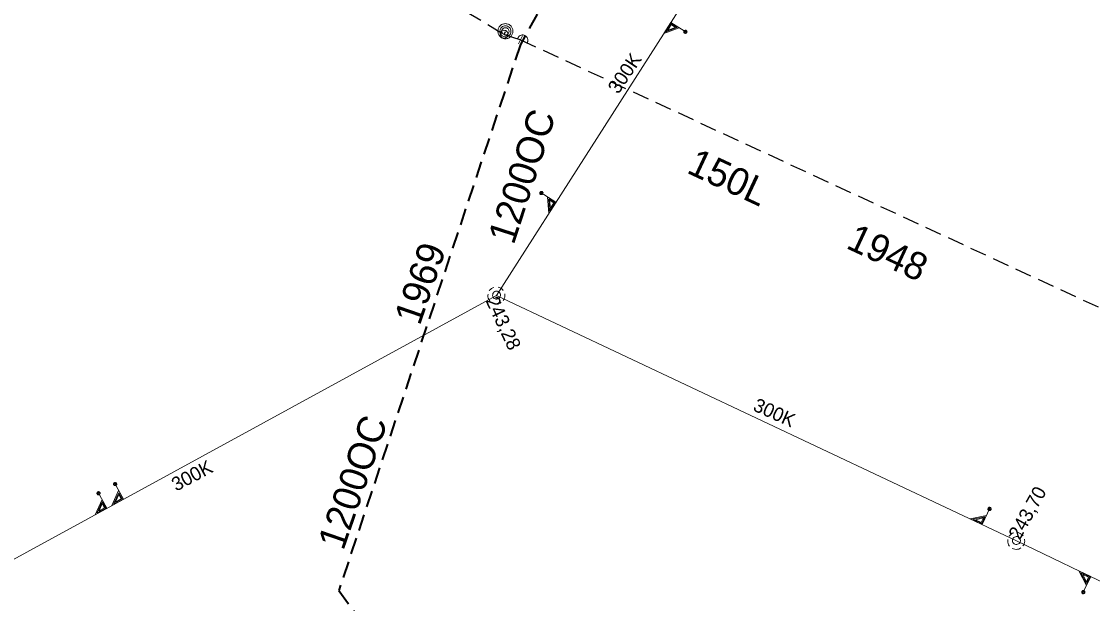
# Model space of a CAD drawing. Extents: x -735085 to -733500, y -1044153 to -1043402.
# Drawn here: x -734712.5 to -734650.3, y -1043643.2 to -1043609.3 of the extents above; entities that cross this region are included whole.
import ezdxf

# ---------------------------------------------------------------- set-up
doc = ezdxf.new("R2010")
doc.units = 0
doc.header["$LTSCALE"] = 0.32
doc.linetypes.add('MEDIUM_DASHED', pattern=[4.5, 3, -1.5])
doc.layers.add('15', color=7, linetype='Continuous')
doc.layers.add('16', color=7, linetype='Continuous')
for name, color, linetype, lineweight in [('18', 7, 'Continuous', 13), ('20', 7, 'Continuous', 13), ('8', 7, 'Continuous', 13)]:
    doc.layers.add(name, color=color, linetype=linetype, lineweight=lineweight)

msp = doc.modelspace()

# ---------------------------------------------------------------- linework, layer by layer
at = {"layer": '18'}
for points in [[(-734673.843, -1043609.992), (-734674.766, -1043609.403), (-734675.181, -1043610.053), (-734674.279, -1043609.714)], [(-734674.406, -1043609.693), (-734674.757, -1043609.469), (-734675.062, -1043609.946), (-734674.405, -1043609.694)], [(-734674.502, -1043609.688), (-734674.748, -1043609.531), (-734674.947, -1043609.844), (-734674.501, -1043609.687)], [(-734682.366, -1043619.262), (-734681.443, -1043619.851), (-734681.857, -1043620.5), (-734681.93, -1043619.54)], [(-734681.857, -1043619.646), (-734681.507, -1043619.87), (-734681.811, -1043620.347), (-734681.858, -1043619.645)], [(-734681.812, -1043619.731), (-734681.566, -1043619.888), (-734681.766, -1043620.201), (-734681.811, -1043619.73)], [(-734685.043, -1043624.797), (-734685.114, -1043624.825), (-734685.181, -1043624.864), (-734685.241, -1043624.912), (-734685.292, -1043624.969), (-734685.316, -1043625.003)], [(-734684.502, -1043624.98), (-734684.552, -1043624.922), (-734684.61, -1043624.872), (-734684.675, -1043624.831), (-734684.746, -1043624.802), (-734684.795, -1043624.788)], [(-734685.388, -1043625.189), (-734685.394, -1043625.266), (-734685.389, -1043625.343), (-734685.372, -1043625.418), (-734685.343, -1043625.489), (-734685.303, -1043625.555), (-734685.287, -1043625.577)], [(-734684.507, -1043625.566), (-734684.466, -1043625.501), (-734684.435, -1043625.431), (-734684.416, -1043625.356), (-734684.408, -1043625.28), (-734684.413, -1043625.203), (-734684.419, -1043625.168)], [(-734685.13, -1043625.706), (-734685.06, -1043625.737), (-734684.985, -1043625.756), (-734684.909, -1043625.763), (-734684.832, -1043625.758), (-734684.757, -1043625.741), (-734684.685, -1043625.713), (-734684.625, -1043625.678)], [(-734708.053, -1043636.676), (-734707.528, -1043637.637), (-734708.203, -1043638.007), (-734707.805, -1043637.13)], [(-734707.088, -1043636.148), (-734706.563, -1043637.109), (-734707.238, -1043637.479), (-734706.84, -1043636.602)], [(-734706.827, -1043636.729), (-734706.628, -1043637.094), (-734707.124, -1043637.366), (-734706.828, -1043636.729)], [(-734707.792, -1043637.257), (-734707.593, -1043637.622), (-734708.089, -1043637.894), (-734707.793, -1043637.257)], [(-734707.793, -1043637.354), (-734707.653, -1043637.61), (-734707.98, -1043637.788), (-734707.792, -1043637.353)], [(-734706.828, -1043636.826), (-734706.688, -1043637.082), (-734707.015, -1043637.26), (-734706.827, -1043636.825)], [(-734656.218, -1043637.586), (-734656.686, -1043638.576), (-734657.382, -1043638.247), (-734656.439, -1043638.053)], [(-734656.534, -1043638.139), (-734656.712, -1043638.515), (-734657.224, -1043638.273), (-734656.534, -1043638.138)], [(-734656.613, -1043638.194), (-734656.738, -1043638.458), (-734657.074, -1043638.3), (-734656.612, -1043638.195)], [(-734654.852, -1043639.057), (-734654.923, -1043639.085), (-734654.99, -1043639.124), (-734655.05, -1043639.172), (-734655.101, -1043639.229), (-734655.125, -1043639.263)], [(-734654.311, -1043639.24), (-734654.361, -1043639.182), (-734654.419, -1043639.132), (-734654.484, -1043639.091), (-734654.555, -1043639.062), (-734654.604, -1043639.048)], [(-734655.197, -1043639.449), (-734655.203, -1043639.526), (-734655.198, -1043639.603), (-734655.181, -1043639.678), (-734655.152, -1043639.749), (-734655.112, -1043639.815), (-734655.096, -1043639.837)], [(-734654.316, -1043639.826), (-734654.275, -1043639.761), (-734654.244, -1043639.691), (-734654.225, -1043639.616), (-734654.217, -1043639.54), (-734654.222, -1043639.463), (-734654.228, -1043639.428)], [(-734654.939, -1043639.966), (-734654.869, -1043639.997), (-734654.794, -1043640.016), (-734654.718, -1043640.023), (-734654.641, -1043640.018), (-734654.566, -1043640.001), (-734654.494, -1043639.973), (-734654.434, -1043639.938)], [(-734650.854, -1043642.594), (-734650.378, -1043641.608), (-734651.072, -1043641.273), (-734650.63, -1043642.129)], [(-734650.624, -1043642), (-734650.443, -1043641.625), (-734650.952, -1043641.379), (-734650.625, -1043642.001)], [(-734650.63, -1043641.904), (-734650.503, -1043641.641), (-734650.837, -1043641.48), (-734650.629, -1043641.905)]]:
    msp.add_lwpolyline(points, dxfattribs=at)
for points in [[(-734673.973, -1043610.022), (-734673.942, -1043610.035), (-734673.909, -1043610.036), (-734673.877, -1043610.025), (-734673.851, -1043610.004), (-734673.834, -1043609.975), (-734673.829, -1043609.942), (-734673.834, -1043609.909), (-734673.852, -1043609.88), (-734673.877, -1043609.859), (-734673.91, -1043609.849), (-734673.943, -1043609.85), (-734673.974, -1043609.863), (-734673.998, -1043609.886), (-734674.013, -1043609.916), (-734674.017, -1043609.949), (-734674.008, -1043609.982), (-734673.989, -1043610.009)], [(-734673.96, -1043609.998), (-734673.933, -1043610.008), (-734673.905, -1043610.006), (-734673.88, -1043609.993), (-734673.863, -1043609.97), (-734673.857, -1043609.943), (-734673.861, -1043609.915), (-734673.877, -1043609.892), (-734673.902, -1043609.877), (-734673.93, -1043609.875), (-734673.957, -1043609.883), (-734673.979, -1043609.902), (-734673.99, -1043609.927), (-734673.989, -1043609.956), (-734673.978, -1043609.982)], [(-734682.337, -1043619.392), (-734682.306, -1043619.405), (-734682.272, -1043619.406), (-734682.241, -1043619.395), (-734682.215, -1043619.374), (-734682.198, -1043619.345), (-734682.192, -1043619.312), (-734682.198, -1043619.279), (-734682.216, -1043619.25), (-734682.242, -1043619.23), (-734682.273, -1043619.219), (-734682.307, -1043619.22), (-734682.338, -1043619.233), (-734682.362, -1043619.256), (-734682.378, -1043619.286), (-734682.381, -1043619.32), (-734682.372, -1043619.352), (-734682.353, -1043619.379)], [(-734682.322, -1043619.37), (-734682.295, -1043619.38), (-734682.267, -1043619.379), (-734682.242, -1043619.364), (-734682.225, -1043619.342), (-734682.218, -1043619.315), (-734682.224, -1043619.287), (-734682.24, -1043619.264), (-734682.264, -1043619.25), (-734682.292, -1043619.246), (-734682.319, -1043619.255), (-734682.34, -1043619.274), (-734682.352, -1043619.3), (-734682.351, -1043619.328), (-734682.34, -1043619.353)], [(-734684.659, -1043625.249), (-734684.665, -1043625.197), (-734684.683, -1043625.147), (-734684.711, -1043625.103), (-734684.749, -1043625.066), (-734684.794, -1043625.039), (-734684.844, -1043625.023), (-734684.896, -1043625.018), (-734684.948, -1043625.025), (-734684.997, -1043625.044), (-734685.041, -1043625.074), (-734685.076, -1043625.113), (-734685.102, -1043625.158), (-734685.117, -1043625.209), (-734685.12, -1043625.261), (-734685.112, -1043625.313), (-734685.091, -1043625.361), (-734685.061, -1043625.404), (-734685.021, -1043625.439), (-734684.975, -1043625.463), (-734684.924, -1043625.477), (-734684.872, -1043625.479), (-734684.82, -1043625.469), (-734684.772, -1043625.447), (-734684.73, -1043625.415), (-734684.697, -1043625.375), (-734684.673, -1043625.328), (-734684.661, -1043625.277)], [(-734708.091, -1043636.804), (-734708.07, -1043636.83), (-734708.041, -1043636.847), (-734708.008, -1043636.853), (-734707.975, -1043636.847), (-734707.946, -1043636.83), (-734707.925, -1043636.804), (-734707.915, -1043636.772), (-734707.916, -1043636.738), (-734707.929, -1043636.708), (-734707.951, -1043636.683), (-734707.982, -1043636.668), (-734708.015, -1043636.665), (-734708.047, -1043636.673), (-734708.076, -1043636.692), (-734708.095, -1043636.72), (-734708.102, -1043636.752), (-734708.098, -1043636.785)], [(-734708.066, -1043636.792), (-734708.048, -1043636.814), (-734708.023, -1043636.826), (-734707.995, -1043636.825), (-734707.968, -1043636.815), (-734707.949, -1043636.794), (-734707.941, -1043636.767), (-734707.944, -1043636.739), (-734707.958, -1043636.715), (-734707.981, -1043636.698), (-734708.009, -1043636.693), (-734708.036, -1043636.699), (-734708.059, -1043636.716), (-734708.072, -1043636.742), (-734708.074, -1043636.769)], [(-734707.126, -1043636.276), (-734707.105, -1043636.302), (-734707.076, -1043636.319), (-734707.043, -1043636.325), (-734707.01, -1043636.319), (-734706.981, -1043636.302), (-734706.96, -1043636.276), (-734706.95, -1043636.244), (-734706.951, -1043636.21), (-734706.964, -1043636.18), (-734706.986, -1043636.155), (-734707.017, -1043636.14), (-734707.05, -1043636.137), (-734707.082, -1043636.145), (-734707.111, -1043636.164), (-734707.13, -1043636.192), (-734707.137, -1043636.224), (-734707.133, -1043636.257)], [(-734707.101, -1043636.264), (-734707.083, -1043636.286), (-734707.058, -1043636.298), (-734707.03, -1043636.297), (-734707.003, -1043636.287), (-734706.984, -1043636.266), (-734706.976, -1043636.239), (-734706.979, -1043636.211), (-734706.993, -1043636.187), (-734707.016, -1043636.17), (-734707.044, -1043636.165), (-734707.071, -1043636.171), (-734707.094, -1043636.188), (-734707.107, -1043636.214), (-734707.109, -1043636.241)], [(-734656.343, -1043637.631), (-734656.352, -1043637.663), (-734656.349, -1043637.696), (-734656.334, -1043637.727), (-734656.31, -1043637.749), (-734656.279, -1043637.762), (-734656.246, -1043637.764), (-734656.213, -1043637.754), (-734656.187, -1043637.733), (-734656.17, -1043637.705), (-734656.164, -1043637.672), (-734656.169, -1043637.639), (-734656.186, -1043637.61), (-734656.212, -1043637.589), (-734656.244, -1043637.577), (-734656.277, -1043637.578), (-734656.308, -1043637.591), (-734656.333, -1043637.613)], [(-734656.319, -1043637.643), (-734656.326, -1043637.671), (-734656.321, -1043637.699), (-734656.304, -1043637.721), (-734656.28, -1043637.736), (-734656.252, -1043637.739), (-734656.225, -1043637.729), (-734656.204, -1043637.711), (-734656.193, -1043637.685), (-734656.193, -1043637.657), (-734656.205, -1043637.632), (-734656.226, -1043637.613), (-734656.253, -1043637.604), (-734656.282, -1043637.609), (-734656.305, -1043637.623)], [(-734654.468, -1043639.509), (-734654.474, -1043639.457), (-734654.492, -1043639.407), (-734654.52, -1043639.363), (-734654.558, -1043639.326), (-734654.603, -1043639.299), (-734654.653, -1043639.283), (-734654.705, -1043639.278), (-734654.757, -1043639.285), (-734654.806, -1043639.304), (-734654.85, -1043639.334), (-734654.885, -1043639.373), (-734654.911, -1043639.418), (-734654.926, -1043639.469), (-734654.929, -1043639.521), (-734654.921, -1043639.573), (-734654.9, -1043639.621), (-734654.87, -1043639.664), (-734654.83, -1043639.699), (-734654.784, -1043639.723), (-734654.733, -1043639.737), (-734654.681, -1043639.739), (-734654.629, -1043639.729), (-734654.581, -1043639.707), (-734654.539, -1043639.675), (-734654.506, -1043639.635), (-734654.482, -1043639.588), (-734654.47, -1043639.537)], [(-734650.899, -1043642.468), (-734650.908, -1043642.501), (-734650.905, -1043642.534), (-734650.891, -1043642.564), (-734650.867, -1043642.587), (-734650.836, -1043642.601), (-734650.803, -1043642.603), (-734650.77, -1043642.593), (-734650.744, -1043642.572), (-734650.726, -1043642.544), (-734650.72, -1043642.511), (-734650.725, -1043642.478), (-734650.741, -1043642.449), (-734650.767, -1043642.428), (-734650.798, -1043642.416), (-734650.832, -1043642.416), (-734650.863, -1043642.429), (-734650.889, -1043642.451)], [(-734650.874, -1043642.478), (-734650.881, -1043642.506), (-734650.875, -1043642.534), (-734650.86, -1043642.557), (-734650.835, -1043642.572), (-734650.807, -1043642.575), (-734650.78, -1043642.567), (-734650.759, -1043642.548), (-734650.747, -1043642.522), (-734650.748, -1043642.494), (-734650.759, -1043642.468), (-734650.781, -1043642.449), (-734650.807, -1043642.441), (-734650.835, -1043642.445), (-734650.86, -1043642.459)]]:
    msp.add_lwpolyline(points, close=True, dxfattribs=at)
at = {"layer": '20'}
for p, q in [((-734668.739, -1043599.96), (-734684.89, -1043625.26)), ((-734668.739, -1043599.96), (-734684.89, -1043625.26)), ((-734684.89, -1043625.26), (-734716.17, -1043642.37)), ((-734684.89, -1043625.26), (-734716.17, -1043642.37)), ((-734654.699, -1043639.52), (-734684.89, -1043625.26)), ((-734654.699, -1043639.52), (-734684.89, -1043625.26)), ((-734623.989, -1043654.36), (-734654.699, -1043639.52)), ((-734623.989, -1043654.36), (-734654.699, -1043639.52))]:
    msp.add_line(p, q, dxfattribs=at)
at = {"layer": '8', "linetype": 'MEDIUM_DASHED', "lineweight": 25}
for p, q in [((-734686.629, -1043608.78), (-734684.458, -1043610.098)), ((-734684.458, -1043610.098), (-734684.37, -1043609.92)), ((-734684.458, -1043610.098), (-734683.5, -1043610.41))]:
    msp.add_line(p, q, dxfattribs=at)
at = {"layer": '8'}
msp.add_line((-734683.39, -1043610.174), (-734683.608, -1043610.643), dxfattribs=at)
at = {"layer": '8', "linetype": 'MEDIUM_DASHED', "lineweight": 35}
msp.add_lwpolyline([(-734668.849, -1043580.305), (-734675.546, -1043596.328), (-734683.508, -1043610.677), (-734694.054, -1043642.408), (-734687.381, -1043651.433), (-734629.763, -1043729.041), (-734628.401, -1043750.135), (-734626.521, -1043774.035)], dxfattribs=at)
at = {"layer": '8'}
for points in [[(-734683.94, -1043609.909), (-734683.942, -1043609.864), (-734683.949, -1043609.819), (-734683.961, -1043609.774), (-734683.977, -1043609.732), (-734683.998, -1043609.691), (-734684.023, -1043609.652), (-734684.052, -1043609.617), (-734684.084, -1043609.584), (-734684.12, -1043609.556), (-734684.157, -1043609.531), (-734684.199, -1043609.51), (-734684.242, -1043609.493), (-734684.286, -1043609.481), (-734684.331, -1043609.474), (-734684.377, -1043609.472), (-734684.423, -1043609.474), (-734684.468, -1043609.481), (-734684.512, -1043609.493), (-734684.555, -1043609.51), (-734684.596, -1043609.531), (-734684.634, -1043609.556), (-734684.67, -1043609.584), (-734684.702, -1043609.617), (-734684.731, -1043609.652), (-734684.756, -1043609.691), (-734684.777, -1043609.732), (-734684.793, -1043609.774), (-734684.805, -1043609.819), (-734684.812, -1043609.864), (-734684.815, -1043609.91), (-734684.812, -1043609.955), (-734684.805, -1043610), (-734684.793, -1043610.045), (-734684.777, -1043610.087), (-734684.756, -1043610.128), (-734684.731, -1043610.167), (-734684.702, -1043610.202), (-734684.67, -1043610.235), (-734684.634, -1043610.263), (-734684.596, -1043610.288), (-734684.555, -1043610.309), (-734684.512, -1043610.326), (-734684.468, -1043610.337), (-734684.423, -1043610.345), (-734684.377, -1043610.347), (-734684.331, -1043610.345), (-734684.286, -1043610.337), (-734684.242, -1043610.326), (-734684.199, -1043610.309), (-734684.157, -1043610.288), (-734684.12, -1043610.263), (-734684.084, -1043610.235), (-734684.052, -1043610.202), (-734684.023, -1043610.167), (-734683.998, -1043610.128), (-734683.977, -1043610.087), (-734683.961, -1043610.045), (-734683.949, -1043610), (-734683.942, -1043609.955), (-734683.94, -1043609.91)], [(-734683.099, -1043610.56), (-734683.087, -1043610.53), (-734683.079, -1043610.5), (-734683.073, -1043610.469), (-734683.072, -1043610.437), (-734683.073, -1043610.406), (-734683.077, -1043610.373), (-734683.085, -1043610.343), (-734683.096, -1043610.313), (-734683.11, -1043610.284), (-734683.128, -1043610.257), (-734683.147, -1043610.233), (-734683.17, -1043610.21), (-734683.193, -1043610.19), (-734683.22, -1043610.172), (-734683.248, -1043610.157), (-734683.278, -1043610.146), (-734683.308, -1043610.137), (-734683.339, -1043610.131), (-734683.372, -1043610.13), (-734683.403, -1043610.131), (-734683.435, -1043610.135), (-734683.466, -1043610.143), (-734683.496, -1043610.154), (-734683.523, -1043610.168), (-734683.552, -1043610.186), (-734683.576, -1043610.205), (-734683.599, -1043610.227), (-734683.619, -1043610.252), (-734683.637, -1043610.278), (-734683.651, -1043610.306)]]:
    msp.add_lwpolyline(points, dxfattribs=at)
for points in [[(-734684.053, -1043609.917), (-734684.059, -1043609.856), (-734684.077, -1043609.796), (-734684.106, -1043609.741), (-734684.145, -1043609.693), (-734684.192, -1043609.653), (-734684.246, -1043609.623), (-734684.305, -1043609.603), (-734684.367, -1043609.596), (-734684.429, -1043609.6), (-734684.489, -1043609.616), (-734684.544, -1043609.644), (-734684.594, -1043609.681), (-734684.635, -1043609.728), (-734684.667, -1043609.781), (-734684.687, -1043609.84), (-734684.697, -1043609.901), (-734684.694, -1043609.963), (-734684.679, -1043610.023), (-734684.653, -1043610.08), (-734684.617, -1043610.13), (-734684.571, -1043610.173), (-734684.519, -1043610.205), (-734684.461, -1043610.228), (-734684.4, -1043610.238), (-734684.338, -1043610.237), (-734684.277, -1043610.224), (-734684.22, -1043610.199), (-734684.169, -1043610.164), (-734684.125, -1043610.12), (-734684.091, -1043610.068), (-734684.067, -1043610.011), (-734684.055, -1043609.95)], [(-734684.227, -1043610.087), (-734684.233, -1043610.035), (-734684.25, -1043609.985), (-734684.279, -1043609.941), (-734684.317, -1043609.904), (-734684.362, -1043609.877), (-734684.412, -1043609.861), (-734684.464, -1043609.856), (-734684.516, -1043609.863), (-734684.565, -1043609.882), (-734684.608, -1043609.912), (-734684.644, -1043609.951), (-734684.67, -1043609.996), (-734684.684, -1043610.047), (-734684.688, -1043610.099), (-734684.679, -1043610.151), (-734684.659, -1043610.199), (-734684.629, -1043610.242), (-734684.589, -1043610.277), (-734684.543, -1043610.301), (-734684.492, -1043610.315), (-734684.44, -1043610.317), (-734684.388, -1043610.307), (-734684.34, -1043610.285), (-734684.298, -1043610.253), (-734684.265, -1043610.213), (-734684.241, -1043610.166), (-734684.228, -1043610.115)], [(-734684.167, -1043609.917), (-734684.173, -1043609.868), (-734684.19, -1043609.821), (-734684.218, -1043609.78), (-734684.256, -1043609.747), (-734684.3, -1043609.723), (-734684.348, -1043609.711), (-734684.398, -1043609.71), (-734684.446, -1043609.722), (-734684.491, -1043609.744), (-734684.529, -1043609.777), (-734684.558, -1043609.817), (-734684.577, -1043609.864), (-734684.584, -1043609.913), (-734684.579, -1043609.963), (-734684.562, -1043610.01), (-734684.535, -1043610.052), (-734684.498, -1043610.086), (-734684.455, -1043610.11), (-734684.407, -1043610.124), (-734684.357, -1043610.125), (-734684.308, -1043610.115), (-734684.263, -1043610.093), (-734684.224, -1043610.061), (-734684.194, -1043610.022), (-734684.175, -1043609.976), (-734684.167, -1043609.926)]]:
    msp.add_lwpolyline(points, close=True, dxfattribs=at)
at = {"layer": '8', "linetype": 'MEDIUM_DASHED', "lineweight": 25}
msp.add_lwpolyline([(-734683.5, -1043610.41), (-734645.881, -1043627.826), (-734643.226, -1043626.851), (-734636.686, -1043612.742)], dxfattribs=at)

# ---------------------------------------------------------------- texts
at = {"layer": '15'}
for s, rotation, p in [('1200OC', 72, (-734683.896, -1043622.374)), ('150L', 335, (-734673.911, -1043618.114)), ('1948', 335, (-734664.659, -1043622.489)), ('1969', 71, (-734689.353, -1043627.066)), ('1200OC', 71, (-734693.79, -1043640.141))]:
    msp.add_text(s, height=1.6, rotation=rotation, dxfattribs=at).set_placement(p)
at = {"layer": '16'}
for s, rotation, p in [('300K', 56, (-734677.821, -1043613.608)), ('243,28', 295, (-734685.545, -1043625.56)), ('300K', 336, (-734670.053, -1043631.93)), ('300K', 28, (-734703.498, -1043636.672)), ('243,70', 61, (-734654.506, -1043639.521))]:
    msp.add_text(s, height=0.8, rotation=rotation, dxfattribs=at).set_placement(p)

doc.saveas('drawing.dxf')
